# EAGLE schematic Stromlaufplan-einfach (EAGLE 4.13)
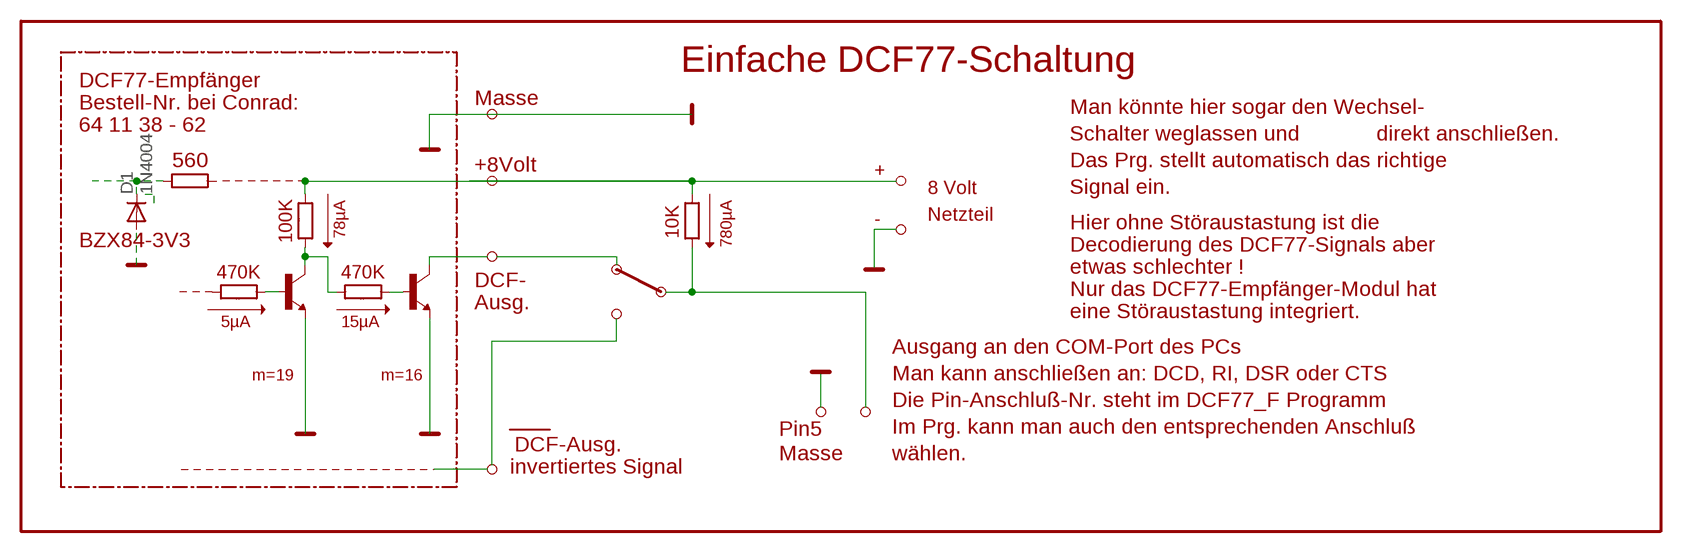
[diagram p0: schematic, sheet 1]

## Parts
D1  1N4004  [DO41-10]

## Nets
N$34: D1.C
N$36: D1.A

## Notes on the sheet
- Einfache DCF77-Schaltung
- DCF77-Empfänger
- Bestell-Nr. bei Conrad: | Masse
- Man könnte hier sogar den Wechsel-
- 64 11 38 - 62
- Schalter weglassen und | direkt anschließen.
- 560 | +8Volt | Das Prg. stellt automatisch das richtige
- +
- 8 Volt | Signal ein.
- - | Netzteil
- Hier ohne Störaustastung ist die
- 100K | 78µA | 10K
- BZX84-3V3 | 780µA | Decodierung des DCF77-Signals aber
- 470K | 470K | etwas schlechter !
- DCF-
- Nur das DCF77-Empfänger-Modul hat
- Ausg.
- eine Störaustastung integriert.
- 5µA | 15µA
- Ausgang an den COM-Port des PCs
- m=19 | m=16 | Man kann anschließen an: DCD, RI, DSR oder CTS
- Die Pin-Anschluß-Nr. steht im DCF77_F Programm
- Pin5 | Im Prg. kann man auch den entsprechenden Anschluß
- DCF-Ausg.
- Masse | wählen.
- invertiertes Signal

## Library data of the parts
D1 = diode:1N4004: DIODE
